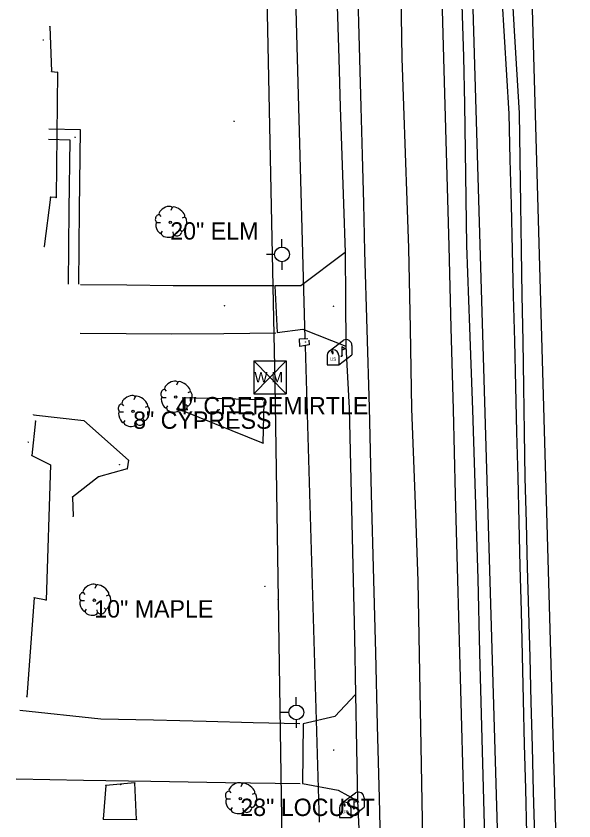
# Model space of a CAD drawing. Extents: x 1930288 to 1941089, y 588389 to 611475.
# Drawn here: x 1930778.8 to 1930939.6, y 597327.2 to 597559.1 of the extents above; entities that cross this region are included whole.
import ezdxf

# ---------------------------------------------------------------- set-up
doc = ezdxf.new("R2010")
doc.units = 0
for name, color, linetype in [('S_BASELINE', 7, 'Continuous'), ('S_BUILDING', 7, 'Continuous'), ('S_DITCHLINE', 7, 'Continuous'), ('S_DRG_PT_SYM', 7, 'Continuous'), ('S_DRIVEWAY', 7, 'Continuous'), ('S_DROP_INLET', 7, 'Continuous'), ('S_EDGE_PAVEMENT', 7, 'Continuous'), ('S_GRD_PT_SYM', 7, 'Continuous'), ('S_LANDSCAPING', 7, 'Continuous'), ('S_MAILBOX', 7, 'Continuous'), ('S_MSC_PT_SYM', 7, 'Continuous'), ('S_PAVEMENT_CROWN', 7, 'Continuous'), ('S_SANITARY_SEWER', 7, 'Continuous'), ('S_SHOULDER', 7, 'Continuous'), ('S_SIDEWALK', 7, 'Continuous'), ('S_STORM_SEWER', 7, 'Continuous'), ('S_STR_PT_SYM', 7, 'Continuous'), ('S_TREE', 7, 'Continuous'), ('S_TREE_ANNOT', 7, 'Continuous'), ('S_UTILITY_POLE', 7, 'Continuous'), ('S_UTL_PT_SYM', 7, 'Continuous'), ('S_WATER_UTILITIES', 7, 'Continuous')]:
    doc.layers.add(name, color=color, linetype=linetype)

msp = doc.modelspace()

# ---------------------------------------------------------------- linework, layer by layer
at = {"layer": 'S_BASELINE'}
msp.add_line((1930922.05, 597172.86), (1930894.27, 598110.49), dxfattribs=at)
at = {"layer": 'S_BUILDING'}
for p, q in [((1930788.52, 597556.12), (1930789.03, 597543.16)), ((1930789.03, 597543.16), (1930790.71, 597542.89)), ((1930790.71, 597542.89), (1930790.28, 597506.8)), ((1930788.66, 597506.88), (1930786.91, 597492.73)), ((1930790.28, 597506.8), (1930788.66, 597506.88)), ((1930784.39, 597442.45), (1930783.35, 597432.49)), ((1930783.35, 597432.49), (1930788.73, 597429.79)), ((1930788.73, 597429.79), (1930787.43, 597390.84)), ((1930784.01, 597391.52), (1930781.9, 597363.01)), ((1930787.43, 597390.84), (1930784.01, 597391.52))]:
    msp.add_line(p, q, dxfattribs=at)
at = {"layer": 'S_DITCHLINE'}
for points in [[(1930928.29, 597322.72), (1930927.95, 597335.64), (1930927.6, 597348.56), (1930927.25, 597361.48), (1930926.91, 597374.4), (1930926.56, 597387.32), (1930926.21, 597400.23), (1930925.87, 597413.15), (1930925.52, 597426.07), (1930925.31, 597439.2), (1930925.1, 597452.32), (1930924.89, 597465.45), (1930924.68, 597478.58), (1930924.47, 597491.7), (1930924.26, 597504.83), (1930924.04, 597517.96), (1930923.83, 597531.08), (1930922.44, 597554.8), (1930921.05, 597578.52)], [(1930925.99, 597323.62), (1930925.67, 597336.44), (1930925.36, 597349.25), (1930925.04, 597362.07), (1930924.73, 597374.88), (1930924.41, 597387.7), (1930924.1, 597400.51), (1930923.78, 597413.33), (1930923.47, 597426.14), (1930923.15, 597439.24), (1930922.82, 597452.33), (1930922.5, 597465.42), (1930922.18, 597478.52), (1930921.86, 597491.61), (1930921.54, 597504.7), (1930921.22, 597517.8), (1930920.9, 597530.89), (1930919.53, 597553.23), (1930918.17, 597575.56)]]:
    msp.add_lwpolyline(points, dxfattribs=at)
at = {"layer": 'S_DRG_PT_SYM'}
msp.add_lwpolyline([(1930862.24, 597465.24), (1930862.24, 597465.29), (1930862.24, 597465.24), (1930862.19, 597465.24), (1930862.24, 597465.24), (1930862.24, 597465.19), (1930862.24, 597465.24), (1930862.29, 597465.24)], dxfattribs=at)
at = {"layer": 'S_DRIVEWAY'}
for points in [[(1930873.62, 597491), (1930860.84, 597481.4), (1930853.37, 597481.38), (1930853.98, 597467.89), (1930861.41, 597468.87), (1930873.84, 597463.99)], [(1930853.04, 597481.36), (1930838.56, 597481.38), (1930824.08, 597481.39), (1930810.71, 597481.54), (1930797.34, 597481.69)], [(1930797.22, 597467.77), (1930810.46, 597467.66), (1930823.69, 597467.55), (1930838.65, 597467.69), (1930853.62, 597467.83)], [(1930876.64, 597363.68), (1930870.69, 597357.29), (1930861.5, 597355.2), (1930861.33, 597337.99), (1930871.64, 597336.06), (1930877.23, 597332.98)], [(1930860.58, 597355.19), (1930847.07, 597355.53), (1930833.56, 597355.88), (1930818.38, 597356.21), (1930803.2, 597356.55), (1930779.83, 597359)], [(1930778.78, 597339.31), (1930798.19, 597338.99), (1930817.6, 597338.67), (1930839.12, 597338.34), (1930860.64, 597338.02)]]:
    msp.add_lwpolyline(points, dxfattribs=at)
at = {"layer": 'S_DROP_INLET'}
msp.add_lwpolyline([(1930863.11, 597465.77), (1930863.29, 597464.37), (1930860.52, 597463.94), (1930860.48, 597466.06), (1930862.89, 597466.22)], dxfattribs=at)
at = {"layer": 'S_EDGE_PAVEMENT'}
for points in [[(1930877.12, 597571.29), (1930877.79, 597546.75), (1930878.16, 597532.87), (1930878.52, 597518.99), (1930878.88, 597505.11), (1930879.24, 597491.23), (1930879.87, 597468.78), (1930880.5, 597446.33), (1930881.15, 597421.48), (1930881.8, 597396.64), (1930882.34, 597375.68), (1930882.87, 597354.72), (1930883.41, 597333.75), (1930883.95, 597312.79)], [(1930901.33, 597571.38), (1930901.97, 597547), (1930902.34, 597533.46), (1930902.72, 597519.92), (1930903.09, 597506.37), (1930903.47, 597492.83), (1930904.09, 597469.27), (1930904.71, 597445.71), (1930905.35, 597421.21), (1930905.99, 597396.7), (1930906.56, 597375.54), (1930907.14, 597354.38), (1930907.71, 597333.22), (1930908.28, 597312.07)]]:
    msp.add_lwpolyline(points, dxfattribs=at)
at = {"layer": 'S_GRD_PT_SYM'}
for points in [[(1930826.82, 597449.07), (1930826.82, 597449.12), (1930826.82, 597449.07), (1930826.77, 597449.07), (1930826.82, 597449.07), (1930826.82, 597449.02), (1930826.82, 597449.07), (1930826.87, 597449.07)], [(1930849.81, 597448.58), (1930849.81, 597448.63), (1930849.81, 597448.58), (1930849.76, 597448.58), (1930849.81, 597448.58), (1930849.81, 597448.53), (1930849.81, 597448.58), (1930849.86, 597448.58)], [(1930850.26, 597447.91), (1930850.26, 597447.96), (1930850.26, 597447.91), (1930850.21, 597447.91), (1930850.26, 597447.91), (1930850.26, 597447.86), (1930850.26, 597447.91), (1930850.31, 597447.91)], [(1930783.81, 597444.24), (1930783.81, 597444.29), (1930783.81, 597444.24), (1930783.76, 597444.24), (1930783.81, 597444.24), (1930783.81, 597444.19), (1930783.81, 597444.24), (1930783.86, 597444.24)], [(1930826.9, 597445.38), (1930826.9, 597445.43), (1930826.9, 597445.38), (1930826.85, 597445.38), (1930826.9, 597445.38), (1930826.9, 597445.33), (1930826.9, 597445.38), (1930826.95, 597445.38)], [(1930798.34, 597442.56), (1930798.34, 597442.61), (1930798.34, 597442.56), (1930798.29, 597442.56), (1930798.34, 597442.56), (1930798.34, 597442.51), (1930798.34, 597442.56), (1930798.39, 597442.56)], [(1930849.96, 597436.08), (1930849.96, 597436.13), (1930849.96, 597436.08), (1930849.91, 597436.08), (1930849.96, 597436.08), (1930849.96, 597436.03), (1930849.96, 597436.08), (1930850.01, 597436.08)], [(1930811.22, 597431.13), (1930811.22, 597431.18), (1930811.22, 597431.13), (1930811.17, 597431.13), (1930811.22, 597431.13), (1930811.22, 597431.08), (1930811.22, 597431.13), (1930811.27, 597431.13)], [(1930810.82, 597428.7), (1930810.82, 597428.75), (1930810.82, 597428.7), (1930810.77, 597428.7), (1930810.82, 597428.7), (1930810.82, 597428.65), (1930810.82, 597428.7), (1930810.87, 597428.7)], [(1930802.52, 597426.34), (1930802.52, 597426.39), (1930802.52, 597426.34), (1930802.46, 597426.34), (1930802.52, 597426.34), (1930802.52, 597426.29), (1930802.52, 597426.34), (1930802.56, 597426.34)], [(1930795.04, 597420.52), (1930795.04, 597420.57), (1930795.04, 597420.52), (1930794.99, 597420.52), (1930795.04, 597420.52), (1930795.04, 597420.47), (1930795.04, 597420.52), (1930795.09, 597420.52)], [(1930795.21, 597415), (1930795.21, 597415.05), (1930795.21, 597415), (1930795.16, 597415), (1930795.21, 597415), (1930795.21, 597414.95), (1930795.21, 597415), (1930795.26, 597415)], [(1930804.6, 597337.47), (1930804.6, 597337.52), (1930804.6, 597337.47), (1930804.55, 597337.47), (1930804.6, 597337.47), (1930804.6, 597337.42), (1930804.6, 597337.47), (1930804.65, 597337.47)], [(1930813.05, 597338.19), (1930813.05, 597338.24), (1930813.05, 597338.19), (1930813, 597338.19), (1930813.05, 597338.19), (1930813.05, 597338.14), (1930813.05, 597338.19), (1930813.1, 597338.19)], [(1930803.89, 597327.75), (1930803.89, 597327.8), (1930803.89, 597327.75), (1930803.84, 597327.75), (1930803.89, 597327.75), (1930803.89, 597327.7), (1930803.89, 597327.75), (1930803.94, 597327.75)], [(1930813.51, 597327.64), (1930813.51, 597327.69), (1930813.51, 597327.64), (1930813.46, 597327.64), (1930813.51, 597327.64), (1930813.51, 597327.59), (1930813.51, 597327.64), (1930813.56, 597327.64)]]:
    msp.add_lwpolyline(points, dxfattribs=at)
at = {"layer": 'S_LANDSCAPING'}
for p, q in [((1930849.81, 597448.58), (1930826.82, 597449.07)), ((1930826.82, 597449.07), (1930826.9, 597445.38)), ((1930849.96, 597436.08), (1930850.26, 597447.91)), ((1930783.81, 597444.24), (1930798.34, 597442.56)), ((1930826.9, 597445.38), (1930849.96, 597436.08)), ((1930798.34, 597442.56), (1930811.22, 597431.13)), ((1930811.22, 597431.13), (1930810.82, 597428.7)), ((1930810.82, 597428.7), (1930802.52, 597426.34)), ((1930802.52, 597426.34), (1930795.04, 597420.52)), ((1930795.04, 597420.52), (1930795.21, 597415)), ((1930804.6, 597337.47), (1930803.89, 597327.75)), ((1930813.05, 597338.19), (1930804.6, 597337.47)), ((1930813.51, 597327.64), (1930813.05, 597338.19)), ((1930803.89, 597327.75), (1930813.51, 597327.64))]:
    msp.add_line(p, q, dxfattribs=at)
at = {"layer": 'S_MAILBOX'}
for p, q in [((1930869, 597462.59), (1930873.14, 597465.7)), ((1930875.57, 597464.22), (1930875.57, 597461.51)), ((1930872.62, 597463.88), (1930872.62, 597461.16)), ((1930868.45, 597461.32), (1930868.45, 597458.6)), ((1930871.77, 597458.6), (1930875.57, 597461.51)), ((1930871.77, 597461.32), (1930871.77, 597458.6)), ((1930868.45, 597458.6), (1930871.77, 597458.6)), ((1930872.52, 597332.23), (1930876.65, 597335.34)), ((1930876.13, 597333.52), (1930876.13, 597330.8)), ((1930879.08, 597333.86), (1930879.08, 597331.15)), ((1930871.96, 597330.95), (1930871.96, 597328.24)), ((1930875.29, 597328.24), (1930879.08, 597331.15)), ((1930875.29, 597330.95), (1930875.29, 597328.24)), ((1930871.96, 597328.24), (1930875.29, 597328.24))]:
    msp.add_line(p, q, dxfattribs=at)
for points in [[(1930869.63, 597462.43), (1930869.85, 597462.29), (1930869.85, 597461.9), (1930870.16, 597461.9), (1930870.16, 597462.26), (1930869.96, 597462.51), (1930869.63, 597462.46)], [(1930872.62, 597463.88), (1930873.73, 597463.21), (1930872.62, 597462.87)], [(1930873.15, 597332.07), (1930873.37, 597331.93), (1930873.37, 597331.54), (1930873.67, 597331.54), (1930873.67, 597331.9), (1930873.48, 597332.15), (1930873.15, 597332.1)], [(1930876.13, 597333.52), (1930877.24, 597332.85), (1930876.13, 597332.5)]]:
    msp.add_lwpolyline(points, dxfattribs=at)
for centre, end in [((1930873.91, 597464.22), 117.5718), ((1930870.11, 597461.32), 180), ((1930877.42, 597333.86), 117.5718), ((1930873.63, 597330.95), 180)]:
    msp.add_arc(centre, 1.66, 0, end, dxfattribs=at)
for centre in [(1930872.62, 597461.16), (1930876.13, 597330.8)]:
    msp.add_ellipse(centre, major_axis=(0.145, 0.132), ratio=0.564646, dxfattribs=at)
at = {"layer": 'S_MSC_PT_SYM'}
for points in [[(1930786.61, 597552.2), (1930786.61, 597552.25), (1930786.61, 597552.2), (1930786.56, 597552.2), (1930786.61, 597552.2), (1930786.61, 597552.15), (1930786.61, 597552.2), (1930786.66, 597552.2)], [(1930841.61, 597528.81), (1930841.61, 597528.86), (1930841.61, 597528.81), (1930841.56, 597528.81), (1930841.61, 597528.81), (1930841.61, 597528.76), (1930841.61, 597528.81), (1930841.66, 597528.81)], [(1930795.77, 597524.18), (1930795.77, 597524.23), (1930795.77, 597524.18), (1930795.72, 597524.18), (1930795.77, 597524.18), (1930795.77, 597524.13), (1930795.77, 597524.18), (1930795.82, 597524.18)], [(1930838.84, 597475.66), (1930838.84, 597475.71), (1930838.84, 597475.66), (1930838.79, 597475.66), (1930838.84, 597475.66), (1930838.84, 597475.61), (1930838.84, 597475.66), (1930838.89, 597475.66)], [(1930870.23, 597475.49), (1930870.23, 597475.54), (1930870.23, 597475.49), (1930870.18, 597475.49), (1930870.23, 597475.49), (1930870.23, 597475.44), (1930870.23, 597475.49), (1930870.28, 597475.49)], [(1930861.97, 597466.22), (1930861.97, 597466.27), (1930861.97, 597466.22), (1930861.92, 597466.22), (1930861.97, 597466.22), (1930861.97, 597466.17), (1930861.97, 597466.22), (1930862.02, 597466.22)], [(1930862.1, 597464.02), (1930862.1, 597464.07), (1930862.1, 597464.02), (1930862.05, 597464.02), (1930862.1, 597464.02), (1930862.1, 597463.97), (1930862.1, 597464.02), (1930862.15, 597464.02)], [(1930837.33, 597445.74), (1930837.33, 597445.79), (1930837.33, 597445.74), (1930837.28, 597445.74), (1930837.33, 597445.74), (1930837.33, 597445.69), (1930837.33, 597445.74), (1930837.38, 597445.74)], [(1930782.27, 597436.36), (1930782.27, 597436.41), (1930782.27, 597436.36), (1930782.22, 597436.36), (1930782.27, 597436.36), (1930782.27, 597436.31), (1930782.27, 597436.36), (1930782.32, 597436.36)], [(1930808.6, 597429.93), (1930808.6, 597429.98), (1930808.6, 597429.93), (1930808.55, 597429.93), (1930808.6, 597429.93), (1930808.6, 597429.88), (1930808.6, 597429.93), (1930808.65, 597429.93)], [(1930850.52, 597394.84), (1930850.52, 597394.89), (1930850.52, 597394.84), (1930850.47, 597394.84), (1930850.52, 597394.84), (1930850.52, 597394.79), (1930850.52, 597394.84), (1930850.57, 597394.84)], [(1930870.33, 597347.63), (1930870.33, 597347.68), (1930870.33, 597347.63), (1930870.28, 597347.63), (1930870.33, 597347.63), (1930870.33, 597347.58), (1930870.33, 597347.63), (1930870.38, 597347.63)], [(1930808.94, 597337.72), (1930808.94, 597337.77), (1930808.94, 597337.72), (1930808.89, 597337.72), (1930808.94, 597337.72), (1930808.94, 597337.67), (1930808.94, 597337.72), (1930808.99, 597337.72)]]:
    msp.add_lwpolyline(points, dxfattribs=at)
at = {"layer": 'S_PAVEMENT_CROWN'}
msp.add_lwpolyline([(1930889.54, 597571.36), (1930890, 597546.92), (1930890.48, 597533.26), (1930890.96, 597519.59), (1930891.43, 597505.93), (1930891.91, 597492.26), (1930892.35, 597469.13), (1930892.79, 597445.99), (1930893.66, 597421.14), (1930894.54, 597396.29), (1930894.92, 597375.15), (1930895.31, 597354.01), (1930895.7, 597332.87), (1930896.08, 597311.73)], dxfattribs=at)
at = {"layer": 'S_SANITARY_SEWER'}
msp.add_line((1930939.56, 597140.44), (1930923.55, 597706.51), dxfattribs=at)
at = {"layer": 'S_SHOULDER'}
for points in [[(1930871.07, 597571.18), (1930871.77, 597546.85), (1930872.23, 597532.89), (1930872.7, 597518.93), (1930873.16, 597504.96), (1930873.62, 597491), (1930873.73, 597477.5), (1930873.84, 597463.99), (1930874.75, 597446.16), (1930875.35, 597421.39), (1930875.96, 597396.62), (1930876.3, 597380.15), (1930876.64, 597363.68), (1930876.94, 597348.33), (1930877.23, 597332.98), (1930878.17, 597312.83)], [(1930907.01, 597571.39), (1930907.77, 597547.31), (1930907.98, 597533.73), (1930908.19, 597520.16), (1930908.4, 597506.58), (1930908.62, 597493), (1930909.45, 597469.35), (1930910.29, 597445.7), (1930911.06, 597421.32), (1930911.83, 597396.93), (1930912.39, 597375.68), (1930912.95, 597354.43), (1930913.51, 597333.17), (1930914.07, 597311.92)]]:
    msp.add_lwpolyline(points, dxfattribs=at)
at = {"layer": 'S_SIDEWALK'}
for points in [[(1930796.9, 597481.86), (1930797.08, 597503.37), (1930797.38, 597526.27), (1930788.19, 597526.49)], [(1930793.9, 597481.88), (1930794.08, 597503.4), (1930794.34, 597523.34), (1930788.12, 597523.49)]]:
    msp.add_lwpolyline(points, dxfattribs=at)
at = {"layer": 'S_STORM_SEWER'}
for p, q in [((1930859.23, 597567.99), (1930861.97, 597466.22)), ((1930862.1, 597464.02), (1930866.13, 597326.83))]:
    msp.add_line(p, q, dxfattribs=at)
at = {"layer": 'S_STR_PT_SYM'}
for points in [[(1930788.52, 597556.12), (1930788.52, 597556.17), (1930788.52, 597556.12), (1930788.47, 597556.12), (1930788.52, 597556.12), (1930788.52, 597556.07), (1930788.52, 597556.12), (1930788.57, 597556.12)], [(1930789.03, 597543.16), (1930789.03, 597543.21), (1930789.03, 597543.16), (1930788.98, 597543.16), (1930789.03, 597543.16), (1930789.03, 597543.11), (1930789.03, 597543.16), (1930789.08, 597543.16)], [(1930790.71, 597542.89), (1930790.71, 597542.94), (1930790.71, 597542.89), (1930790.66, 597542.89), (1930790.71, 597542.89), (1930790.71, 597542.84), (1930790.71, 597542.89), (1930790.76, 597542.89)], [(1930788.66, 597506.88), (1930788.66, 597506.93), (1930788.66, 597506.88), (1930788.61, 597506.88), (1930788.66, 597506.88), (1930788.66, 597506.83), (1930788.66, 597506.88), (1930788.71, 597506.88)], [(1930790.28, 597506.8), (1930790.28, 597506.85), (1930790.28, 597506.8), (1930790.23, 597506.8), (1930790.28, 597506.8), (1930790.28, 597506.75), (1930790.28, 597506.8), (1930790.33, 597506.8)], [(1930786.91, 597492.73), (1930786.91, 597492.78), (1930786.91, 597492.73), (1930786.86, 597492.73), (1930786.91, 597492.73), (1930786.91, 597492.68), (1930786.91, 597492.73), (1930786.96, 597492.73)], [(1930784.39, 597442.45), (1930784.39, 597442.5), (1930784.39, 597442.45), (1930784.34, 597442.45), (1930784.39, 597442.45), (1930784.39, 597442.4), (1930784.39, 597442.45), (1930784.44, 597442.45)], [(1930783.35, 597432.49), (1930783.35, 597432.54), (1930783.35, 597432.49), (1930783.3, 597432.49), (1930783.35, 597432.49), (1930783.35, 597432.44), (1930783.35, 597432.49), (1930783.4, 597432.49)], [(1930788.73, 597429.79), (1930788.73, 597429.84), (1930788.73, 597429.79), (1930788.68, 597429.79), (1930788.73, 597429.79), (1930788.73, 597429.74), (1930788.73, 597429.79), (1930788.78, 597429.79)], [(1930784.01, 597391.52), (1930784.01, 597391.57), (1930784.01, 597391.52), (1930783.96, 597391.52), (1930784.01, 597391.52), (1930784.01, 597391.47), (1930784.01, 597391.52), (1930784.06, 597391.52)], [(1930787.43, 597390.84), (1930787.43, 597390.89), (1930787.43, 597390.84), (1930787.38, 597390.84), (1930787.43, 597390.84), (1930787.43, 597390.79), (1930787.43, 597390.84), (1930787.48, 597390.84)], [(1930781.9, 597363.01), (1930781.9, 597363.06), (1930781.9, 597363.01), (1930781.85, 597363.01), (1930781.9, 597363.01), (1930781.9, 597362.96), (1930781.9, 597363.01), (1930781.95, 597363.01)]]:
    msp.add_lwpolyline(points, dxfattribs=at)
at = {"layer": 'S_TREE'}
for p, q in [((1930823.77, 597503.93), (1930823.39, 597503.08)), ((1930819.98, 597501.92), (1930820.48, 597501.34)), ((1930827.34, 597501.14), (1930826.68, 597500.87)), ((1930819.32, 597499.59), (1930820.44, 597499.59)), ((1930820.48, 597496.42), (1930820.94, 597497.11)), ((1930824.16, 597496.14), (1930824.08, 597496.92)), ((1930826.56, 597497.04), (1930826.1, 597497.46)), ((1930825.36, 597453.59), (1930824.97, 597452.74)), ((1930821.56, 597451.58), (1930822.07, 597451)), ((1930828.93, 597450.8), (1930828.27, 597450.53)), ((1930813.06, 597449.43), (1930812.68, 597448.58)), ((1930820.91, 597449.25), (1930822.03, 597449.25)), ((1930809.27, 597447.42), (1930809.77, 597446.84)), ((1930816.63, 597446.64), (1930815.97, 597446.37)), ((1930822.07, 597446.08), (1930822.53, 597446.77)), ((1930825.75, 597445.81), (1930825.67, 597446.58)), ((1930828.15, 597446.7), (1930827.69, 597447.12)), ((1930808.61, 597445.09), (1930809.73, 597445.09)), ((1930809.77, 597441.91), (1930810.24, 597442.61)), ((1930813.45, 597441.64), (1930813.37, 597442.42)), ((1930815.85, 597442.53), (1930815.39, 597442.96)), ((1930801.87, 597395.07), (1930801.48, 597394.22)), ((1930798.07, 597393.05), (1930798.58, 597392.47)), ((1930805.43, 597392.28), (1930804.78, 597392.01)), ((1930797.41, 597390.73), (1930798.54, 597390.73)), ((1930798.58, 597387.55), (1930799.04, 597388.25)), ((1930802.26, 597387.28), (1930802.18, 597388.06)), ((1930804.66, 597388.17), (1930804.19, 597388.6)), ((1930843.95, 597337.9), (1930843.57, 597337.05)), ((1930840.16, 597335.88), (1930840.66, 597335.3)), ((1930847.52, 597335.11), (1930846.86, 597334.84)), ((1930839.5, 597333.56), (1930840.62, 597333.56)), ((1930840.66, 597330.38), (1930841.13, 597331.08)), ((1930844.34, 597330.11), (1930844.26, 597330.89)), ((1930846.74, 597331), (1930846.28, 597331.43))]:
    msp.add_line(p, q, dxfattribs=at)
for centre in [(1930823.21, 597499.69), (1930824.8, 597449.35), (1930812.51, 597445.19), (1930801.31, 597390.82), (1930843.4, 597333.65)]:
    msp.add_circle(centre, 0.341, dxfattribs=at)
for centre, major_axis, ratio, start_param, end_param in [((1930821.88, 597502.89), (1.86, 1.08), 0.471018, 0, 3.141593), ((1930825.53, 597502.57), (-1.81, 1.36), 0.405113, 3.141593, 6.283186), ((1930819.64, 597500.78), (0.31, 1.03), 0.646762, 0, 3.141593), ((1930826.89, 597499.16), (0.46, 2.04), 0.482994, 3.141593, 6.283185), ((1930819.95, 597498.12), (-0.61, 1.6), 0.420543, 6.283185, 9.424777), ((1930822.41, 597496.34), (-1.83, 0.19), 0.529943, 0, 3.141593), ((1930825.37, 597496.64), (1.09, 0.46), 0.711534, 3.141592, 6.283185), ((1930823.47, 597452.55), (1.86, 1.08), 0.471018, 0, 3.141593), ((1930827.12, 597452.23), (-1.81, 1.36), 0.405113, 3.141593, 6.283186), ((1930821.23, 597450.44), (0.31, 1.03), 0.646762, 0, 3.141593), ((1930828.48, 597448.82), (0.46, 2.04), 0.482994, 3.141593, 6.283185), ((1930811.17, 597448.39), (1.86, 1.08), 0.471018, 0, 3.141593), ((1930814.82, 597448.06), (-1.81, 1.36), 0.405113, 3.141593, 6.283186), ((1930821.54, 597447.79), (-0.61, 1.6), 0.420543, 6.283185, 9.424777), ((1930808.94, 597446.27), (0.31, 1.03), 0.646762, 0, 3.141593), ((1930816.18, 597444.66), (0.46, 2.04), 0.482994, 3.141593, 6.283185), ((1930824, 597446.01), (-1.83, 0.19), 0.529943, 0, 3.141593), ((1930826.96, 597446.3), (1.09, 0.46), 0.711534, 3.141592, 6.283185), ((1930809.24, 597443.62), (-0.61, 1.6), 0.420543, 6.283185, 9.424777), ((1930811.7, 597441.84), (-1.83, 0.19), 0.529943, 0, 3.141593), ((1930814.66, 597442.14), (1.09, 0.46), 0.711534, 3.141592, 6.283185), ((1930799.97, 597394.03), (1.86, 1.08), 0.471018, 0, 3.141593), ((1930803.63, 597393.7), (-1.81, 1.36), 0.405113, 3.141593, 6.283186), ((1930797.74, 597391.91), (0.31, 1.03), 0.646762, 0, 3.141593), ((1930804.98, 597390.29), (0.46, 2.04), 0.482994, 3.141593, 6.283185), ((1930798.05, 597389.26), (-0.61, 1.6), 0.420543, 6.283185, 9.424777), ((1930800.51, 597387.48), (-1.83, 0.19), 0.529943, 0, 3.141593), ((1930803.46, 597387.77), (1.09, 0.46), 0.711534, 3.141592, 6.283185), ((1930842.06, 597336.86), (1.86, 1.08), 0.471018, 0, 3.141593), ((1930845.71, 597336.53), (-1.81, 1.36), 0.405113, 3.141593, 6.283186), ((1930839.83, 597334.74), (0.31, 1.03), 0.646762, 0, 3.141593), ((1930847.07, 597333.12), (0.46, 2.04), 0.482994, 3.141593, 6.283185), ((1930840.13, 597332.09), (-0.61, 1.6), 0.420543, 6.283185, 9.424777), ((1930842.59, 597330.31), (-1.83, 0.19), 0.529943, 0, 3.141593), ((1930845.55, 597330.6), (1.09, 0.46), 0.711534, 3.141592, 6.283185)]:
    msp.add_ellipse(centre, major_axis=major_axis, ratio=ratio, start_param=start_param, end_param=end_param, dxfattribs=at)
at = {"layer": 'S_UTILITY_POLE'}
for p, q in [((1930855.41, 597492.54), (1930855.41, 597494.78)), ((1930853.32, 597490.41), (1930850.99, 597490.41)), ((1930855.49, 597485.99), (1930855.49, 597488.31)), ((1930859.54, 597360.6), (1930859.54, 597362.85)), ((1930857.45, 597358.47), (1930855.12, 597358.47)), ((1930859.62, 597354.05), (1930859.62, 597356.38))]:
    msp.add_line(p, q, dxfattribs=at)
for centre in [(1930855.41, 597490.43), (1930859.54, 597358.49)]:
    msp.add_circle(centre, 2.13, dxfattribs=at)
at = {"layer": 'S_UTL_PT_SYM'}
for points in [[(1930861.97, 597466.22), (1930861.97, 597466.27), (1930861.97, 597466.22), (1930861.92, 597466.22), (1930861.97, 597466.22), (1930861.97, 597466.17), (1930861.97, 597466.22), (1930862.02, 597466.22)], [(1930862.1, 597464.02), (1930862.1, 597464.07), (1930862.1, 597464.02), (1930862.05, 597464.02), (1930862.1, 597464.02), (1930862.1, 597463.97), (1930862.1, 597464.02), (1930862.15, 597464.02)], [(1930862.24, 597465.24), (1930862.24, 597465.29), (1930862.24, 597465.24), (1930862.19, 597465.24), (1930862.24, 597465.24), (1930862.24, 597465.19), (1930862.24, 597465.24), (1930862.29, 597465.24)], [(1930853.31, 597453.42), (1930853.31, 597453.47), (1930853.31, 597453.42), (1930853.26, 597453.42), (1930853.31, 597453.42), (1930853.31, 597453.37), (1930853.31, 597453.42), (1930853.36, 597453.42)], [(1930854.35, 597391.03), (1930854.35, 597391.08), (1930854.35, 597391.03), (1930854.3, 597391.03), (1930854.35, 597391.03), (1930854.35, 597390.98), (1930854.35, 597391.03), (1930854.4, 597391.03)]]:
    msp.add_lwpolyline(points, dxfattribs=at)
at = {"layer": 'S_WATER_UTILITIES'}
for p, q in [((1930850.82, 597577.28), (1930853.31, 597453.42)), ((1930847.27, 597459.77), (1930856.6, 597459.77)), ((1930847.27, 597459.77), (1930847.27, 597450.28)), ((1930847.27, 597459.77), (1930856.6, 597450.28)), ((1930856.6, 597459.77), (1930847.27, 597450.28)), ((1930856.6, 597459.77), (1930856.6, 597450.28)), ((1930853.31, 597453.42), (1930854.35, 597391.03)), ((1930847.27, 597450.28), (1930856.6, 597450.28)), ((1930854.35, 597391.03), (1930856.29, 597254.36))]:
    msp.add_line(p, q, dxfattribs=at)

# ---------------------------------------------------------------- texts
at = {"layer": 'S_MAILBOX'}
for p in [(1930869.21, 597459.79), (1930872.73, 597329.43)]:
    msp.add_text('US', height=0.96, rotation=360, dxfattribs=at).set_placement(p)
at = {"layer": 'S_TREE_ANNOT'}
for s, p in [('20" ELM', (1930823.21, 597494.69)), ('4" CREPEMIRTLE', (1930824.8, 597444.35)), ('8" CYPRESS', (1930812.51, 597440.19)), ('10" MAPLE', (1930801.31, 597385.82)), ('28" LOCUST', (1930843.4, 597328.65))]:
    msp.add_text(s, height=5, dxfattribs=at).set_placement(p)
at = {"layer": 'S_WATER_UTILITIES'}
msp.add_text('W M', height=3, rotation=360, dxfattribs=at).set_placement((1930847.47, 597453.54))

doc.saveas('drawing.dxf')
